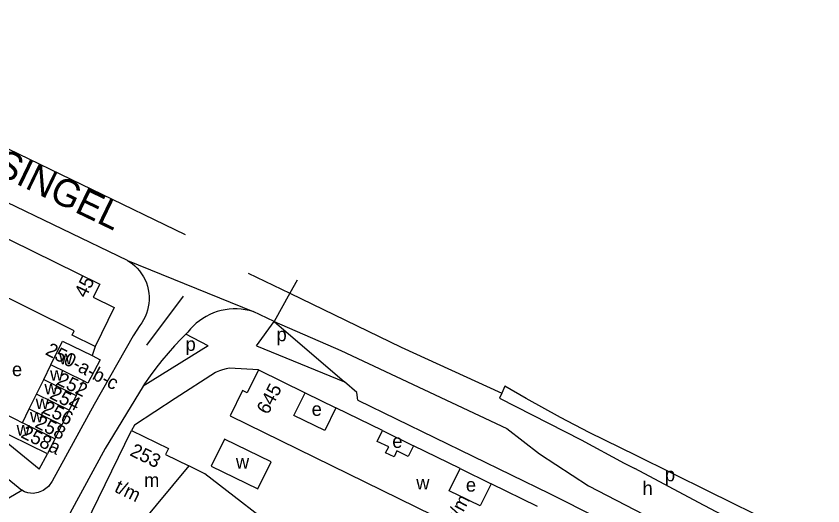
# Model space of a CAD drawing. Extents: x 159045 to 160918, y 380454 to 382516.
# Drawn here: x 160288.7 to 160524.1, y 381978.4 to 382121.4 of the extents above; entities that cross this region are included whole.
import ezdxf

# ---------------------------------------------------------------- set-up
doc = ezdxf.new("R2010")
doc.units = 0
for name, color, linetype in [('BLT_Basislijn', 7, 'Continuous'), ('BLT_Bebouwing', 7, 'Continuous'), ('BLT_Centroide', 7, 'Continuous'), ('BLT_Huisnummer', 7, 'Continuous'), ('BLT_Huisnummer_ tussenligend', 7, 'Continuous'), ('BLT_Huisnummer_reeks', 7, 'Continuous'), ('BLT_Onderverdeling_panden', 7, 'Continuous'), ('BLT_Straatnaam_hoofdweg', 7, 'Continuous'), ('BLT_Vlakafsluiter', 7, 'Continuous')]:
    doc.layers.add(name, color=color, linetype=linetype)

msp = doc.modelspace()

# ---------------------------------------------------------------- linework, layer by layer
at = {"layer": 'BLT_Basislijn'}
for p, q in [((160277.26, 382086.91), (160337.98, 382057.61)), ((160321.19, 382050.06), (160267.3, 382075.9)), ((160356.41, 382046.36), (160368.56, 382040.48)), ((160337.45, 382039.61), (160326.74, 382025.32)), ((160368.56, 382040.48), (160401.06, 382024.75)), ((160364.01, 382032.24), (160357.84, 382035.1)), ((160358.8, 382025.14), (160364.01, 382032.24)), ((160364.01, 382032.24), (160384.51, 382014.57)), ((160338.8, 382029.12), (160338.16, 382028.48)), ((160344.73, 382025.12), (160338.16, 382028.48)), ((160311.74, 382024.95), (160310.85, 382022.25)), ((160344.73, 382025.12), (160325.72, 382013.34)), ((160358.8, 382025.14), (160384.51, 382014.57)), ((160401.06, 382024.75), (160430.44, 382011.31)), ((160346.82, 382017.34), (160335.12, 382009.72)), ((160431.34, 382013.33), (160430.44, 382011.31)), ((160373.02, 382011.41), (160382.01, 382006.99)), ((160430.44, 382011.31), (160429.78, 382009.83)), ((160395.64, 382000.34), (160404.63, 381995.93)), ((160490.84, 381982.59), (160469.66, 381993.03)), ((160418.25, 381989.25), (160427.28, 381984.83)), ((160487.8, 381979.39), (160469.24, 381989.26)), ((160525.07, 381965.79), (160490.84, 381982.59)), ((160522.66, 381961.08), (160487.8, 381979.39))]:
    msp.add_line(p, q, dxfattribs=at)
for points in [[(160246.92, 382075.24), (160246.18, 382074.45), (160230.97, 382044.63), (160230.38, 382041), (160230.97, 382036.96), (160242.39, 382017.58), (160253.84, 382012.7), (160290.33, 381982.98)], [(160321.19, 382050.06), (160322.53, 382049.1), (160323.3, 382048.45), (160324.02, 382047.74), (160324.69, 382046.97), (160325.29, 382046.15), (160325.82, 382045.29), (160326.29, 382044.39), (160326.68, 382043.46), (160326.99, 382042.49), (160327.23, 382041.51), (160327.4, 382040.51), (160327.48, 382039.5), (160327.48, 382038.48), (160327.4, 382037.47), (160327.24, 382036.47), (160327.01, 382035.49), (160326.7, 382034.52), (160326.31, 382033.59), (160325.85, 382032.68), (160325.32, 382031.82), (160324.73, 382031.01)], [(160357.84, 382035.1), (160356.7, 382035.41), (160355.55, 382035.65), (160354.38, 382035.81), (160353.2, 382035.89), (160352.02, 382035.9), (160350.84, 382035.82), (160349.67, 382035.66), (160348.52, 382035.42), (160347.38, 382035.11), (160346.26, 382034.71), (160345.18, 382034.25), (160344.13, 382033.71), (160343.12, 382033.1), (160342.15, 382032.43), (160341.23, 382031.69), (160340.36, 382030.89), (160339.55, 382030.03), (160338.8, 382029.12)], [(160324.73, 382031.01), (160322.84, 382028.07), (160311.43, 382007.97), (160299.22, 381985.6), (160298.12, 381984.06), (160296.57, 381982.86), (160295.13, 381982.26), (160293.65, 381982.02), (160292.06, 381982.15), (160291.12, 381982.43), (160290.33, 381982.98)], [(160338.16, 382028.48), (160336.81, 382027.11), (160334.88, 382025.06), (160333.02, 382022.95), (160331.21, 382020.79), (160329.47, 382018.58), (160327.79, 382016.32), (160326.17, 382014.01), (160325.72, 382013.34)], [(160383.42, 382023.75), (160431.85, 382000.98), (160441.45, 381993.61), (160455.73, 381984.23), (160496.12, 381963.24)], [(160359.38, 382018.1), (160350.93, 382018.54), (160349.93, 382018.38), (160348.94, 382018.14), (160347.98, 382017.83), (160347.04, 382017.44), (160346.82, 382017.34)], [(160325.72, 382013.34), (160314.62, 381995.12), (160304.41, 381976.34), (160304.21, 381974), (160304.95, 381971.77), (160306.03, 381969.69), (160306.99, 381968.72)], [(160388.42, 382009.2), (160388.11, 382011.47), (160384.51, 382014.57)], [(160469.66, 381993.03), (160455.93, 381999.75), (160447.54, 382004.15), (160437.53, 382009.71), (160431.34, 382013.33)], [(160335.12, 382009.72), (160323.18, 382001.96), (160322.38, 382000.41)], [(160388.42, 382009.2), (160444.35, 381982), (160500.59, 381953.64)], [(160429.78, 382009.83), (160453.57, 381997.65), (160466.15, 381990.88), (160469.24, 381989.26)], [(160295.35, 381989.05), (160276.03, 382004.81), (160276.54, 382005.44)], [(160295.35, 381989.05), (160297.81, 381993.53)], [(160363.04, 381960.16), (160368.12, 381968.83), (160343.72, 381987.74), (160339.1, 381990.03)]]:
    msp.add_lwpolyline(points, dxfattribs=at)
at = {"layer": 'BLT_Bebouwing'}
for p, q in [((160298.82, 382019.54), (160302.24, 382026.48)), ((160296.72, 382015.27), (160298.82, 382019.54)), ((160359.38, 382018.1), (160373.02, 382011.41)), ((160294.62, 382010.99), (160296.72, 382015.27)), ((160308.32, 382014.87), (160306.22, 382010.6)), ((160309.58, 382014.22), (160308.32, 382014.87)), ((160292.52, 382006.72), (160294.62, 382010.99)), ((160306.22, 382010.6), (160304.11, 382006.33)), ((160290.52, 382002.64), (160292.52, 382006.72)), ((160304.11, 382006.33), (160302.01, 382002.06)), ((160395.64, 382000.34), (160382.01, 382006.99)), ((160302.01, 382002.06), (160299.97, 381997.92)), ((160308.14, 381971.37), (160322.38, 382000.41)), ((160418.25, 381989.25), (160404.63, 381995.93)), ((160339.1, 381990.03), (160319.6, 381966.67)), ((160440.84, 381978.19), (160427.28, 381984.83))]:
    msp.add_line(p, q, dxfattribs=at)
for points in [[(160254.12, 382072.11), (160313.06, 382043.13), (160311.2, 382039.33), (160317.3, 382036.31), (160311.74, 382024.95)], [(160311.74, 382024.95), (160305.02, 382028.18), (160305.63, 382029.45), (160280.18, 382042.02), (160279.52, 382040.69), (160276.02, 382042.41)], [(160302.24, 382026.48), (160310.85, 382022.25)], [(160310.85, 382022.25), (160313.18, 382021.05)], [(160313.18, 382021.05), (160309.58, 382014.22)], [(160359.38, 382018.1), (160356.13, 382011.42), (160354.77, 382012.09), (160351.13, 382004.64), (160488.92, 381937.14), (160492.63, 381944.75), (160482.96, 381949.48), (160486.14, 381955.98)], [(160382.01, 382006.99), (160378.76, 382000.35), (160369.72, 382004.78), (160373.02, 382011.41)], [(160297.81, 381993.53), (160281.53, 382001.51), (160283.78, 382006.05), (160288.3, 382003.82), (160290.52, 382002.64)], [(160322.38, 382000.41), (160333.13, 381995.12), (160332.26, 381993.38), (160339.1, 381990.03)], [(160404.63, 381995.93), (160403.1, 381992.76), (160399.76, 381994.39), (160398.97, 381992.69), (160396.52, 381993.85), (160397.4, 381995.56), (160394.08, 381997.19), (160395.64, 382000.34)], [(160299.97, 381997.92), (160297.81, 381993.53)], [(160427.28, 381984.83), (160424.12, 381978.38), (160415.08, 381982.8), (160418.25, 381989.25)]]:
    msp.add_lwpolyline(points, dxfattribs=at)
msp.add_lwpolyline([(160349.47, 381997.89), (160345.6, 381990), (160359.19, 381983.32), (160363.07, 381991.21)], close=True, dxfattribs=at)
at = {"layer": 'BLT_Onderverdeling_panden'}
for p, q in [((160308.32, 382014.87), (160298.82, 382019.54)), ((160296.72, 382015.27), (160306.22, 382010.6)), ((160304.11, 382006.33), (160294.62, 382010.99)), ((160292.52, 382006.72), (160302.01, 382002.06)), ((160299.97, 381997.92), (160290.52, 382002.64))]:
    msp.add_line(p, q, dxfattribs=at)
at = {"layer": 'BLT_Vlakafsluiter'}
for p, q in [((160321.19, 382050.06), (160357.84, 382035.1)), ((160370.65, 382044.26), (160368.56, 382040.48)), ((160368.56, 382040.48), (160364.01, 382032.24)), ((160364.01, 382032.24), (160383.42, 382023.75)), ((160279.43, 381976.49), (160290.33, 381982.98))]:
    msp.add_line(p, q, dxfattribs=at)

# ---------------------------------------------------------------- texts
at = {"layer": 'BLT_Centroide'}
for s, p in [('p', (160364.67, 382026.44)), ('p', (160338.12, 382023.63)), ('w', (160301.25, 382019.72)), ('e', (160287.46, 382016.25)), ('w', (160298.57, 382014.92)), ('w', (160296.93, 382010.92)), ('w', (160294.36, 382006.64)), ('w', (160292.72, 382002.74)), ('e', (160374.92, 382004.64)), ('w', (160288.8, 381998.9)), ('e', (160398.45, 381995.3)), ('w', (160352.81, 381989.26)), ('m', (160326.01, 381983.9)), ('p', (160478.02, 381985.54)), ('w', (160405.45, 381983.15)), ('e', (160419.94, 381982.53)), ('h', (160471.49, 381981.52))]:
    msp.add_text(s, height=4, dxfattribs=at).set_placement(p)
at = {"layer": 'BLT_Huisnummer'}
for s, p in [('254', (160298.15, 382009.9)), ('258', (160293.86, 382001.46))]:
    msp.add_text(s, height=4, rotation=333.7946, dxfattribs=at).set_placement(p)
at = {"layer": 'BLT_Huisnummer_ tussenligend'}
for s, p in [('252', (160300.23, 382013.99)), ('256', (160296.01, 382005.7))]:
    msp.add_text(s, height=4, rotation=333.7946, dxfattribs=at).set_placement(p)
at = {"layer": 'BLT_Huisnummer_reeks'}
for s, rotation, p in [('45', 63.7964, (160309.03, 382038.85)), ('250-a-b-c', 332.3759, (160296.93, 382022.7)), ('645', 62, (160362.16, 382004.8)), ('258a', 333.7946, (160289.77, 381998.48)), ('253', 333.9355, (160321.6, 381993.22)), ('t/m', 333.9355, (160317.09, 381982.62)), ('t/m', 62, (160417.77, 381973.75))]:
    msp.add_text(s, height=4, rotation=rotation, dxfattribs=at).set_placement(p)
at = {"layer": 'BLT_Straatnaam_hoofdweg'}
msp.add_text('KEIZER KAREL V SINGEL', height=7.9999, rotation=334.3232, dxfattribs=at).set_placement((160200.96, 382114.56))

doc.saveas('drawing.dxf')
